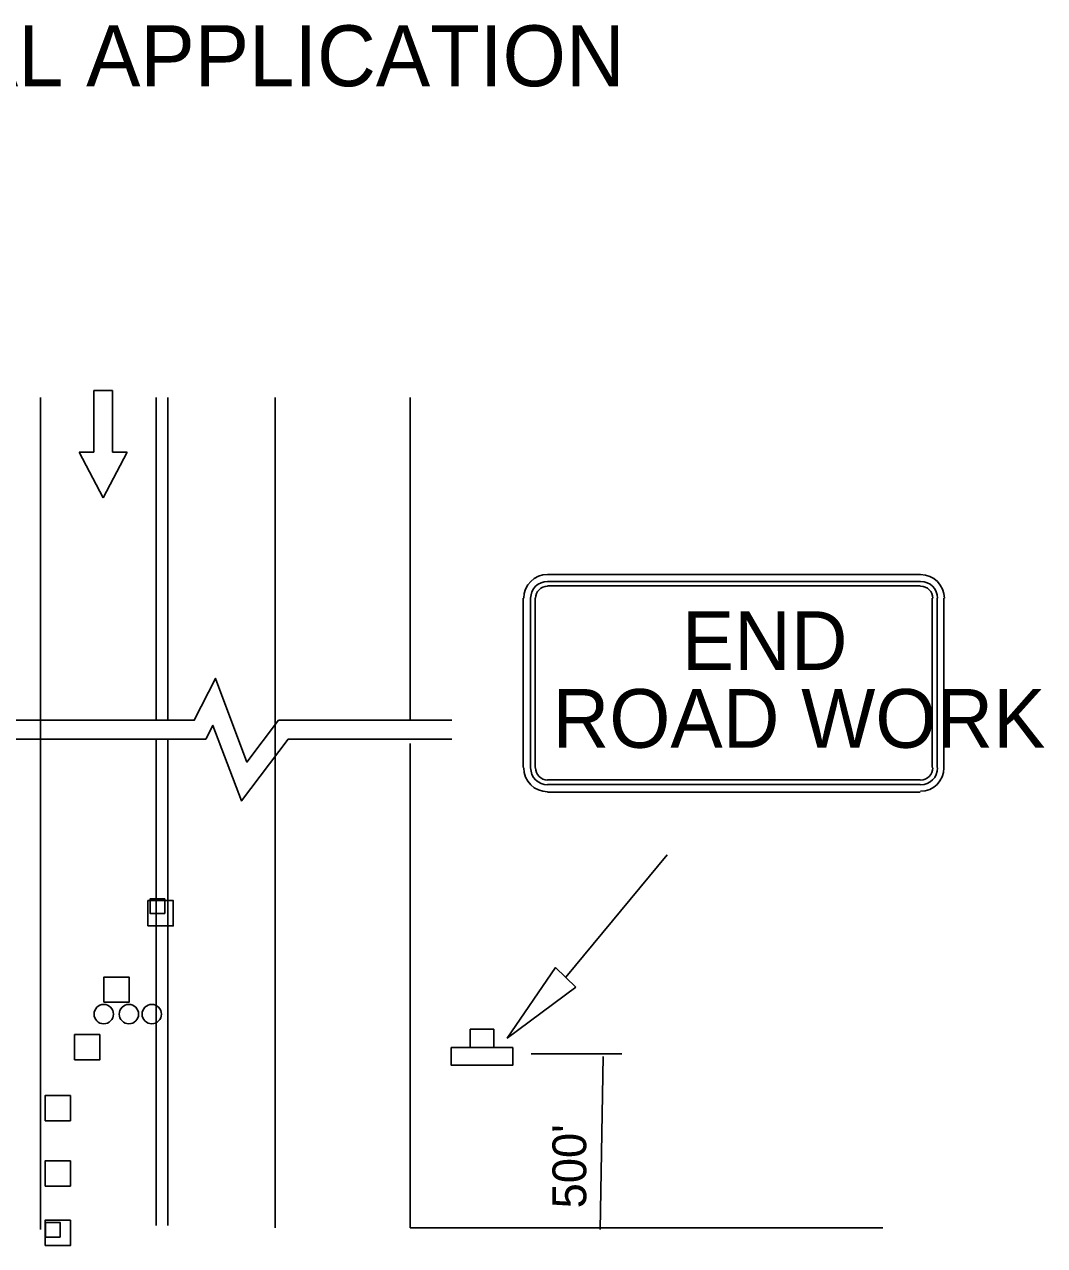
# Model space of a CAD drawing. Extents: x 1531.5 to 1538.6, y 1529.6 to 1539.6.
# Drawn here: x 1535.626 to 1537.435, y 1537.432 to 1539.597 of the extents above; entities that cross this region are included whole.
import ezdxf

# ---------------------------------------------------------------- set-up
doc = ezdxf.new("R2010")
doc.units = 0
for name, color, linetype in [('DETL-DIMS', 7, 'Continuous'), ('DETL-LINE', 7, 'Continuous'), ('DETL-NOTE', 7, 'Continuous'), ('DETL-TITL', 7, 'Continuous'), ('USER-BORD', 7, 'Continuous')]:
    doc.layers.add(name, color=color, linetype=linetype)

# ---------------------------------------------------------------- blocks, each defined once
blk = doc.blocks.new('CD1')
at = {"layer": 'USER-BORD'}
blk.add_lwpolyline([(0, 0.0312), (0.0312, 0.0312), (0.0312, 0), (0, 0)], close=True, dxfattribs=at)
blk = doc.blocks.new('DIR2')
at = {"layer": 'USER-BORD'}
for p, q in [((0, 0.0012), (-0.0342, -0.0477)), ((0, 0.0012), (0.0342, -0.0477)), ((-0.0342, -0.0477), (-0.0132, -0.0477)), ((-0.0132, -0.1133), (-0.0132, -0.0477)), ((0.0342, -0.0477), (0.0132, -0.0477)), ((0.0132, -0.1133), (0.0132, -0.0477)), ((-0.0011, -0.1133), (-0.0132, -0.1133)), ((-0.0011, -0.1133), (0.0011, -0.1133)), ((0.0011, -0.1133), (0.0132, -0.1133))]:
    blk.add_line(p, q, dxfattribs=at)

msp = doc.modelspace()

# ---------------------------------------------------------------- linework, layer by layer
at = {"layer": 'DETL-DIMS'}
for p, q in [((1536.5857, 1537.9075), (1536.7657, 1538.1246)), ((1536.5243, 1537.7718), (1536.6853, 1537.7718)), ((1536.6519, 1537.7667), (1536.6469, 1537.4601))]:
    msp.add_line(p, q, dxfattribs=at)
msp.add_lwpolyline([(1536.6037, 1537.8902), (1536.5677, 1537.9247), (1536.482, 1537.7997)], close=True, dxfattribs=at)
at = {"layer": 'DETL-LINE'}
for p, q in [((1535.6543, 1537.46), (1535.6543, 1538.9357)), ((1535.8595, 1538.9357), (1535.8595, 1538.3631)), ((1535.8801, 1538.9357), (1535.8801, 1538.3631)), ((1536.0705, 1537.4632), (1536.0705, 1538.9357)), ((1536.3098, 1538.9357), (1536.3098, 1538.3631)), ((1537.2145, 1538.6215), (1536.5535, 1538.6215)), ((1537.2145, 1538.6095), (1536.5535, 1538.6095)), ((1537.2145, 1538.6095), (1537.2145, 1538.6095)), ((1536.5535, 1538.6015), (1537.2145, 1538.6015)), ((1536.5105, 1538.5795), (1536.5105, 1538.2795)), ((1536.5235, 1538.2795), (1536.5235, 1538.5795)), ((1536.5315, 1538.5795), (1536.5315, 1538.2795)), ((1537.2355, 1538.2795), (1537.2355, 1538.5795)), ((1537.2445, 1538.5795), (1537.2445, 1538.2795)), ((1537.2565, 1538.2795), (1537.2565, 1538.5795)), ((1535.8595, 1538.3295), (1535.8595, 1537.6585)), ((1535.8801, 1538.3295), (1535.8801, 1537.6585)), ((1536.3098, 1538.3221), (1536.3098, 1537.6511)), ((1536.5537, 1538.2572), (1536.554, 1538.2578)), ((1536.5535, 1538.2575), (1537.2145, 1538.2575)), ((1537.2145, 1538.2495), (1536.5535, 1538.2495)), ((1536.5535, 1538.2355), (1537.2145, 1538.2355)), ((1535.8595, 1537.6672), (1535.8595, 1537.4674)), ((1535.8801, 1537.6672), (1535.8801, 1537.4674)), ((1536.3098, 1537.6598), (1536.3098, 1537.4632)), ((1536.3098, 1537.4632), (1537.1479, 1537.4632))]:
    msp.add_line(p, q, dxfattribs=at)
for points in [[(1535.6543, 1538.81), (1535.6543, 1538.91)], [(1536.0705, 1538.8132), (1536.0705, 1538.9132)], [(1535.6543, 1538.41), (1535.6543, 1538.51)], [(1536.0705, 1538.4132), (1536.0705, 1538.5132)], [(1535.3912, 1538.3631), (1535.927, 1538.3631), (1535.9645, 1538.4373), (1536.0206, 1538.2889), (1536.0767, 1538.3631), (1536.3837, 1538.3631)], [(1535.3912, 1538.3295), (1535.9476, 1538.3295), (1535.9601, 1538.3541), (1536.0107, 1538.2201), (1536.0935, 1538.3295), (1536.3837, 1538.3295)], [(1535.6543, 1538.01), (1535.6543, 1538.11)], [(1536.0705, 1538.0132), (1536.0705, 1538.1132)], [(1535.6543, 1537.61), (1535.6543, 1537.71)], [(1536.0705, 1537.6132), (1536.0705, 1537.7132)]]:
    msp.add_lwpolyline(points, dxfattribs=at)
for points in [[(1535.8449, 1537.9985), (1535.8897, 1537.9985), (1535.8897, 1538.0433), (1535.8449, 1538.0433)], [(1535.7668, 1537.8631), (1535.8116, 1537.8631), (1535.8116, 1537.9079), (1535.7668, 1537.9079)], [(1535.7148, 1537.761), (1535.7596, 1537.761), (1535.7596, 1537.8058), (1535.7148, 1537.8058)], [(1536.4584, 1537.8153), (1536.4165, 1537.8153), (1536.4165, 1537.7828), (1536.4584, 1537.7828)], [(1536.3829, 1537.7828), (1536.3829, 1537.7515), (1536.4919, 1537.7515), (1536.4919, 1537.7828)], [(1535.6627, 1537.653), (1535.7075, 1537.653), (1535.7075, 1537.6978), (1535.6627, 1537.6978)], [(1535.6627, 1537.5371), (1535.7075, 1537.5371), (1535.7075, 1537.5819), (1535.6627, 1537.5819)], [(1535.6627, 1537.4317), (1535.7075, 1537.4317), (1535.7075, 1537.4765), (1535.6627, 1537.4765)]]:
    msp.add_lwpolyline(points, close=True, dxfattribs=at)
for centre in [(1535.7666, 1537.8421), (1535.8112, 1537.8421), (1535.8518, 1537.8421)]:
    msp.add_circle(centre, 0.0172, dxfattribs=at)
for centre, radius, start, end in [((1536.5537, 1538.5794), 0.0424, 90, 180), ((1536.5537, 1538.5794), 0.0301, 90, 180), ((1537.215, 1538.5794), 0.0421, 0, 90), ((1537.215, 1538.5794), 0.0301, 0, 90), ((1536.5537, 1538.5794), 0.0216, 90, 180), ((1537.215, 1538.5794), 0.0216, 0, 90), ((1536.5537, 1538.2788), 0.0424, 180, 270), ((1536.5537, 1538.2788), 0.0301, 180, 270), ((1536.5537, 1538.2788), 0.0216, 180, 270), ((1537.215, 1538.2788), 0.0415, 270, 0), ((1537.215, 1538.2788), 0.0216, 270, 0), ((1537.215, 1538.2788), 0.0301, 270, 0)]:
    msp.add_arc(centre, radius, start, end, dxfattribs=at)

# ---------------------------------------------------------------- block references
at = {"layer": 'DETL-LINE', "xscale": 1.2465521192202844, "yscale": -1.6620694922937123}
msp.add_blockref('DIR2', (1535.7654, 1538.7593), dxfattribs=at)
at = {"layer": 'DETL-LINE', "xscale": 0.8310347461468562, "yscale": 0.8310347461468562, "rotation": 180}
for p in [(1535.8747, 1538.0465), (1535.6895, 1537.4726)]:
    msp.add_blockref('CD1', p, dxfattribs=at)

# ---------------------------------------------------------------- texts
at = {"layer": 'DETL-LINE'}
for s, p in [('END', (1536.7915, 1538.4524)), ('ROAD WORK', (1536.5625, 1538.3144))]:
    msp.add_text(s, height=0.1041, rotation=360, dxfattribs=at).set_placement(p)
at = {"layer": 'DETL-NOTE'}
msp.add_text("500'", height=0.06, rotation=90, dxfattribs=at).set_placement((1536.6222, 1537.4977))
at = {"layer": 'DETL-TITL'}
msp.add_text('TEMPORARY TRAFFIC CONTROL TYPICAL APPLICATION', height=0.108, dxfattribs=at).set_placement((1532.7424, 1539.4874))

doc.saveas('drawing.dxf')
